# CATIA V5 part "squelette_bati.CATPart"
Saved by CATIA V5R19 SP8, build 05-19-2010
Part number: squelette_bati
Publications: "Plan.1", "Plan.2", "Droite.1"
Bounding box of the stored display mesh (mm): x -6 to 0, y 0 to 6.5, z -84 to 0
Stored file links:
  C:\Users\ThinkMotion\Desktop\EU_thinkMotion\iao\IAO_MMS_Groupe3\pmayet\pmayet_avant_optimisation\pmayet_avant_optimisation\squelette_bati.CATPart
  C:\Users\ThinkMotion\Desktop\EU_thinkMotion\iao\IAO_MMS_Groupe3\pmayet\pmayet_avant_optimisation\pmayet_avant_optimisation\squelette.CATProduct
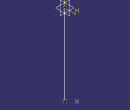
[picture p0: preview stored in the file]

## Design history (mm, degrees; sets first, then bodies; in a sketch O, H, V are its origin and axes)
Set1
  Point1 "PointA": linked copy from another document
  Point2 "PointB": linked copy from another document
  Point3 "Point_origine_aiguille": linked copy from another document
Set2
  Plane1: type OffsetPt, RefPlane yz-plane, RefPoint Point1
  Plane2: type OffsetPt, RefPlane zx-plane, RefPoint Point1
  Line1: type PtPt, FirstPoint Point1, SecondPoint Point2
Body1 (main body)
  Sketch1 on Plane1, origin (0, 0, 0), H (0, 1, 0), V (0, 0, 1)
